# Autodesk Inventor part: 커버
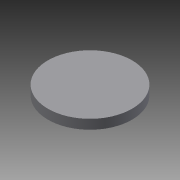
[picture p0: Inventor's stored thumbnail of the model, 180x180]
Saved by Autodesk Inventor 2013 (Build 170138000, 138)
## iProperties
Created: 2015-07
Part Number: 커버
Material: 일반
Document SubType Name: Modeling
Designer: user
Density: 1 g/cm^3
Author: user
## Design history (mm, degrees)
sketch "스케치1"
  geometry: C1 r 40 at (0, 0); 1 further point
  constraints: 1 centre point, 1 coincident
  dimensions: "d0" = 80 diameter of C1
extrude "돌출1" new body sketch "스케치1" distance "d1" = 9; taper "d2" = 0 deg
node "솔리드1"
